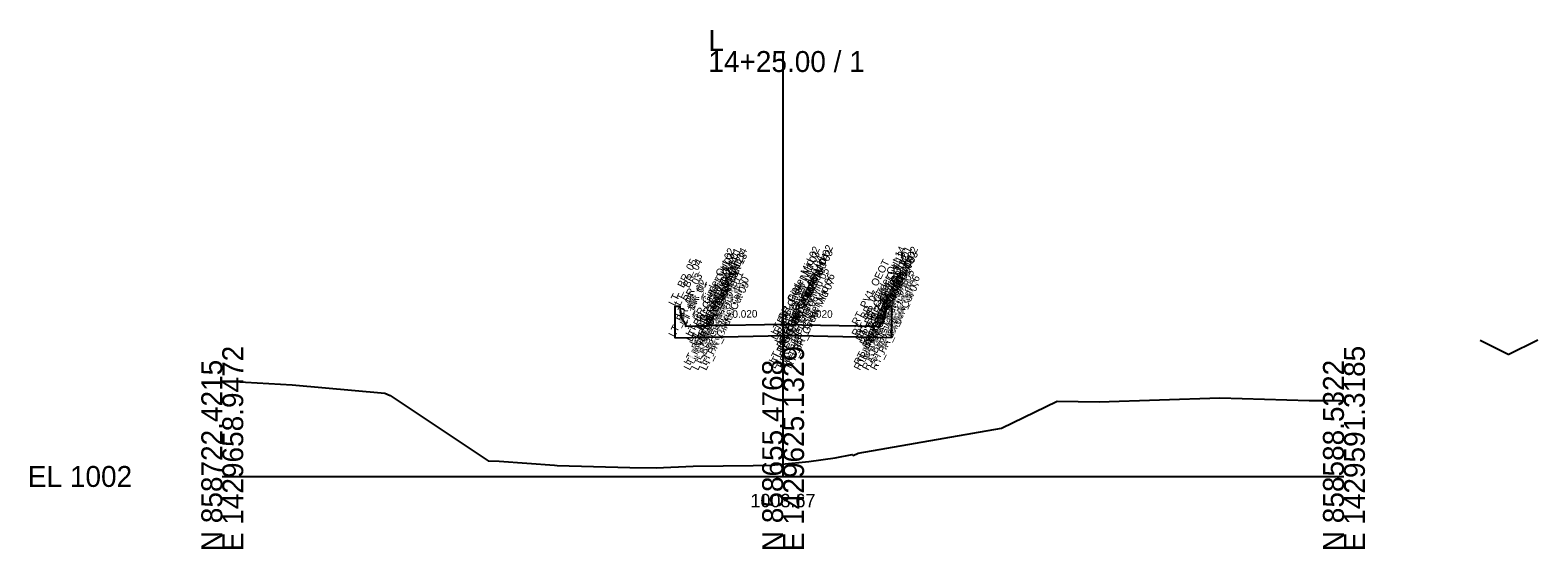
# Model space of a CAD drawing. Extents: x -26 to 176, y -10 to 13058.
# Drawn here: x -25.7 to 175.9, y 5490.3 to 5559.7 of the extents above; entities that cross this region are included whole.
import ezdxf

# ---------------------------------------------------------------- set-up
doc = ezdxf.new("R2010")
doc.units = 0
for name, color, linetype in [('Default', 7, 'Continuous'), ('Exist Cross Section Cell', 7, 'Continuous'), ('Exist XS Center Line Elevation Label', 7, 'Continuous'), ('Exist XS Ground Line', 7, 'Continuous'), ('Prop CMT Concrete Structures', 7, 'Continuous'), ('Prop XS Dump Level', 7, 'Continuous'), ('Prop XS SE Text', 7, 'Continuous')]:
    doc.layers.add(name, color=color, linetype=linetype)

msp = doc.modelspace()

# ---------------------------------------------------------------- linework, layer by layer
at = {"layer": 'Default'}
for q in [(168.22, 5518.19), (175.93, 5518.3)]:
    msp.add_line((171.97, 5516.32), q, dxfattribs=at)
at = {"layer": 'Exist Cross Section Cell'}
for p, q in [((75, 5500), (75, 5556.93)), ((0, 5500), (75, 5500)), ((75, 5500), (150, 5500))]:
    msp.add_line(p, q, dxfattribs=at)
at = {"layer": 'Exist XS Ground Line'}
msp.add_lwpolyline([(0, 5512.79), (9.35, 5512.25), (21.72, 5511.16), (22.46, 5510.85), (35.55, 5502.07), (37.01, 5502.03), (44.44, 5501.49), (44.78, 5501.47), (54.52, 5501.19), (58.03, 5501.14), (62.99, 5501.38), (71.01, 5501.48), (73.39, 5501.51), (74.84, 5501.66), (78.42, 5502.01), (81.97, 5502.51), (84.22, 5502.92), (84.36, 5502.82), (85.04, 5503.11), (104.21, 5506.46), (111.64, 5510.06), (117.26, 5509.98), (133.39, 5510.5), (145.37, 5510.16), (149.53, 5510.15), (150, 5510.14)], dxfattribs=at)
at = {"layer": 'Prop CMT Concrete Structures'}
for points in [[(75, 5520.35), (65, 5520.15), (62, 5520.09), (61.99, 5520.34), (61.41, 5521.17), (61.24, 5522.76), (60.5, 5522.76), (60.5, 5518.56)], [(75, 5520.35), (85, 5520.15), (88, 5520.09), (88.01, 5520.34), (88.59, 5521.17), (88.76, 5522.76), (89.5, 5522.76), (89.5, 5518.56)], [(60.5, 5518.56), (65, 5518.65), (75, 5518.85)], [(75, 5518.85), (75, 5520.35)], [(75, 5518.85), (75, 5520.35)], [(89.5, 5518.56), (85, 5518.65), (75, 5518.85)]]:
    msp.add_lwpolyline(points, dxfattribs=at)

# ---------------------------------------------------------------- texts
at = {"layer": 'Default'}
msp.add_text('-', height=0.0001, dxfattribs=at).set_placement((0, 5500))
at = {"layer": 'Exist Cross Section Cell'}
for s, p in [('L', (65, 5556.93)), ('14+25.00 / 1', (65, 5554.13)), ('EL 1002', (-26, 5498.6))]:
    msp.add_text(s, height=2.8, dxfattribs=at).set_placement(p)
for s, p in [('E 1429658.9472', (2.8, 5490)), ('E 1429625.1329', (77.8, 5490)), ('E 1429591.3185', (152.8, 5490)), ('N 858722.4215', (0, 5490)), ('N 858655.4768', (75, 5490)), ('N 858588.5322', (150, 5490))]:
    msp.add_text(s, height=2.8, rotation=90, dxfattribs=at).set_placement(p)
at = {"layer": 'Exist XS Center Line Elevation Label'}
msp.add_text('1003.67', height=1.8, dxfattribs=at).set_placement((70.63, 5495.87))
msp.add_text('1003.67', height=1.8, dxfattribs=at).set_placement((70.63, 5495.87))
msp.add_text('1003.67', height=1.8, dxfattribs=at).set_placement((70.63, 5495.87))
at = {"layer": 'Prop XS Dump Level'}
for s, p in [('LT_BR_Girder Out 02', (62.79, 5518.61)), ('LT_BR_Girder Out 14', (64.46, 5518.64)), ('LT_BR_Girder Mid 02', (74.17, 5518.83)), ('RT_BR_Girder Mid 02', (75.83, 5518.83)), ('RT_BR_Girder Out 14', (85.54, 5518.64)), ('RT_BR_Girder Out 01', (86.38, 5518.62)), ('RT_BR_Girder Out 02', (87.21, 5518.61)), ('LT_ BR_05', (60.5, 5522.76)), ('LT_ BR_04', (61.24, 5522.76)), ('LT_BR_Girder Out 03', (62.79, 5517.96)), ('LT_BR_Girder Out 04', (63.29, 5517.46)), ('LT_BR_Girder Out 01', (63.62, 5518.62)), ('LT_BR_Girder Out 12', (63.96, 5517.46)), ('LT_BR_Girder Out 13', (64.46, 5517.96)), ('LT_PV1_OEOT', (65, 5520.15)), ('LT_BR_Girder Mid 03', (74.17, 5518.18)), ('LT_BR_Girder Mid 04', (74.67, 5517.68)), ('RT_BR_Girder Mid 04', (75.33, 5517.68)), ('RT_BR_Girder Mid 03', (75.83, 5518.18)), ('RT_PV1_OEOT', (85, 5520.15)), ('RT_BR_Girder Out 13', (85.54, 5517.96)), ('RT_BR_Girder Out 12', (86.04, 5517.46)), ('RT_BR_Girder Out 04', (86.71, 5517.46)), ('RT_BR_Girder Out 03', (87.21, 5517.96)), ('RT_ BR_04', (88.76, 5522.76)), ('RT_ BR_05', (89.5, 5522.76)), ('LT_BR_03', (61.41, 5521.17)), ('LT_BR_Girder Out 06', (62.54, 5514.79)), ('LT_BR_Girder Out 05', (63.29, 5515.54)), ('LT_BR_Girder Out 11', (63.96, 5515.54)), ('LT_BR_Girder Out 10', (64.71, 5514.79)), ('LT_BR_Girder Mid 06', (73.92, 5515.02)), ('LT_BR_Girder Mid 05', (74.67, 5515.77)), ('RT_BR_Girder Mid 05', (75.33, 5515.77)), ('RT_BR_Girder Mid 06', (76.08, 5515.02)), ('RT_BR_Girder Mid 07', (76.08, 5514.35)), ('RT_BR_Girder Out 10', (85.29, 5514.79)), ('RT_BR_Girder Out 11', (86.04, 5515.54)), ('RT_BR_Girder Out 05', (86.71, 5515.54)), ('RT_BR_Girder Out 06', (87.46, 5514.79)), ('RT_BR_02', (88.01, 5520.34)), ('RT_BR_03', (88.59, 5521.17)), ('LT_BR_06', (60.5, 5518.56)), ('LT_BR_02', (61.99, 5520.34)), ('LT_BR_01', (62, 5520.09)), ('LT_BR_Girder Out 07', (62.54, 5514.12)), ('LT_BR_Girder Out 08', (63.62, 5514.12)), ('LT_BR_Girder Out 09', (64.71, 5514.12)), ('LT_BR_07', (65, 5518.65)), ('LT_BR_Girder Mid 07', (73.92, 5514.35)), ('PV1_PGL', (75, 5520.35)), ('RT_BR_07', (85, 5518.65)), ('RT_BR_Girder Out 09', (85.29, 5514.12)), ('RT_BR_Girder Out 08', (86.38, 5514.12)), ('RT_BR_Girder Out 07', (87.46, 5514.12)), ('RT_BR_01', (88, 5520.09)), ('RT_BR_06', (89.5, 5518.56)), ('BR_Girder Mid 08', (75, 5514.35)), ('BR_PGL', (75, 5518.85))]:
    msp.add_text(s, height=1, rotation=63.5833, dxfattribs=at).set_placement(p)
at = {"layer": 'Prop XS SE Text'}
for rotation, p in [(1.1458, (68.23, 5521.22)), (358.8542, (78.27, 5521.29))]:
    msp.add_text('0.020', height=1, rotation=rotation, dxfattribs=at).set_placement(p)

doc.saveas('drawing.dxf')
